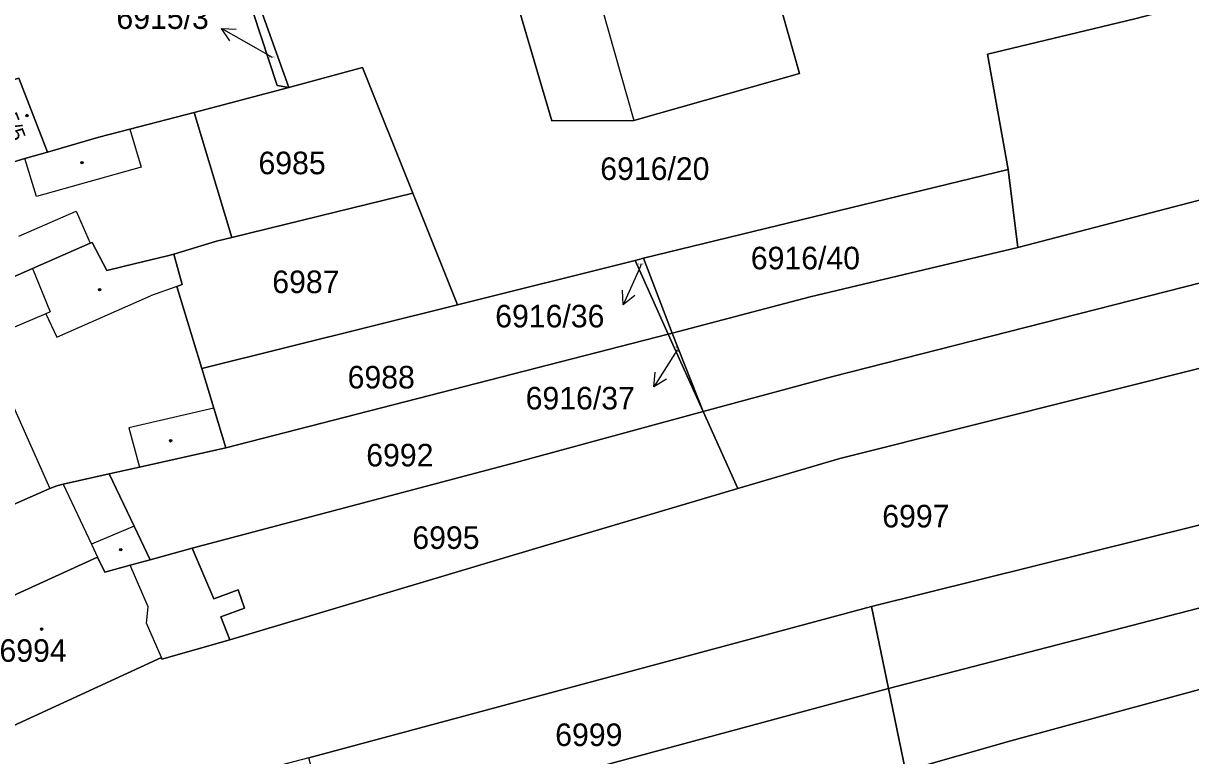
# Model space of a CAD drawing. Extents: x -596233 to -595156, y -1161235 to -1159375.
# Drawn here: x -595331.7 to -595243.9, y -1160372.2 to -1160317 of the extents above; entities that cross this region are included whole.
import ezdxf

# ---------------------------------------------------------------- set-up
doc = ezdxf.new("R2010")
doc.units = 0
for name, color, linetype in [('KN_CAR_KR', 7, 'Continuous'), ('KN_KULTURY', 7, 'Continuous'), ('KN_PARC_CIS_POM', 7, 'Continuous'), ('KN_PARC_CIS_POZ', 7, 'Continuous'), ('KN_PARC_CIS_STAV', 7, 'Continuous'), ('KN_PARC_PLOCHA', 7, 'Continuous'), ('PARC_C_SIPKA', 7, 'Continuous'), ('parcely_l', 7, 'Continuous')]:
    doc.layers.add(name, color=color, linetype=linetype)

msp = doc.modelspace()

# ---------------------------------------------------------------- linework, layer by layer
at = {"layer": 'KN_CAR_KR'}
for points in [[(-595290.5, -1160307.71), (-595285.79, -1160324.36)], [(-595323.72, -1160325.02), (-595322.86, -1160327.88)], [(-595330.75, -1160330.09), (-595331.62, -1160327.22)], [(-595322.86, -1160327.88), (-595330.75, -1160330.09)], [(-595332.06, -1160333.07), (-595327.76, -1160331.18)], [(-595327.76, -1160331.18), (-595326.69, -1160333.61)], [(-595331.05, -1160335.51), (-595329.7, -1160338.77)], [(-595320.18, -1160336.85), (-595322.15, -1160337.57)], [(-595329.21, -1160340.67), (-595322.15, -1160337.57)], [(-595330.03, -1160338.91), (-595334.73, -1160340.9)], [(-595329.7, -1160338.77), (-595330.03, -1160338.91)], [(-595330.03, -1160338.91), (-595329.21, -1160340.67)], [(-595334.73, -1160340.9), (-595329.73, -1160352.08)], [(-595317.4, -1160346.03), (-595323.78, -1160347.51)], [(-595323.78, -1160347.51), (-595323, -1160350.46)], [(-595328.73, -1160351.75), (-595326.59, -1160356.27)], [(-595323.38, -1160354.91), (-595326.59, -1160356.27)], [(-595326.59, -1160356.27), (-595326.14, -1160357.23)], [(-595322.33, -1160360.97), (-595323.68, -1160357.84)], [(-595322.47, -1160362.21), (-595322.33, -1160360.97)], [(-595321.34, -1160364.8), (-595322.47, -1160362.21)]]:
    msp.add_lwpolyline(points, dxfattribs=at)
at = {"layer": 'KN_KULTURY'}
for centre, radius in [((-595331.46, -1160323.99), 0.09), ((-595331.46, -1160323.99), 0.0398), ((-595327.31, -1160327.54), 0.09), ((-595327.31, -1160327.54), 0.0398), ((-595325.99, -1160337.1), 0.09), ((-595325.99, -1160337.1), 0.0398), ((-595320.65, -1160348.48), 0.09), ((-595320.65, -1160348.48), 0.0398), ((-595324.4, -1160356.68), 0.09), ((-595324.4, -1160356.68), 0.0398), ((-595330.36, -1160362.66), 0.09), ((-595330.36, -1160362.66), 0.0398)]:
    msp.add_circle(centre, radius, dxfattribs=at)
at = {"layer": 'KN_PARC_PLOCHA'}
for points in [[(-595326.08, -1160281.97), (-595323.99, -1160287.92), (-595322, -1160293.27), (-595321.7, -1160294.07), (-595312.63, -1160321.74), (-595311.75, -1160321.89), (-595318.88, -1160323.75), (-595323.72, -1160325.02), (-595326.04, -1160325.63), (-595329.91, -1160326.74), (-595332.08, -1160321.19), (-595334.71, -1160321.94), (-595337.01, -1160322.6), (-595346.85, -1160300.58), (-595351.35, -1160290.65), (-595352.68, -1160287.85), (-595328.36, -1160276.46)], [(-595275.52, -1160298.61), (-595273.4, -1160306.13), (-595277.16, -1160307.25), (-595273.32, -1160320.83), (-595285.79, -1160324.36), (-595291.95, -1160324.4), (-595296.39, -1160309.27), (-595296.06, -1160309.19), (-595297.11, -1160305.25), (-595291.63, -1160303.69), (-595295.08, -1160291.51), (-595295.59, -1160289.7), (-595283.15, -1160286.13), (-595279.31, -1160299.71)], [(-595311.75, -1160321.89), (-595312.63, -1160321.74), (-595321.7, -1160294.07)], [(-595199.64, -1160320.07), (-595225.81, -1160325.82), (-595256.9, -1160333.93), (-595257.62, -1160328.05), (-595259.17, -1160319.36), (-595248.1, -1160316.7), (-595204.23, -1160305.26), (-595199.79, -1160319.6)], [(-595197.73, -1160326.01), (-595198.12, -1160326.1), (-595224.64, -1160331.86), (-595270.82, -1160343.63), (-595280.58, -1160346.28), (-595282.9, -1160340.37), (-595272.51, -1160337.64), (-595256.9, -1160333.93), (-595225.81, -1160325.82), (-595199.64, -1160320.07)], [(-595302.43, -1160329.84), (-595308.16, -1160331.23), (-595316.04, -1160333.18), (-595318.88, -1160323.75), (-595311.75, -1160321.89), (-595306.22, -1160320.38)], [(-595329.91, -1160326.74), (-595331.62, -1160327.22), (-595332.53, -1160327.51), (-595334.71, -1160321.94), (-595332.08, -1160321.19)], [(-595316.04, -1160333.18), (-595317.19, -1160333.46), (-595320.41, -1160334.42), (-595320.87, -1160334.56), (-595323.28, -1160335.14), (-595325.46, -1160335.65), (-595326.55, -1160333.55), (-595326.69, -1160333.61), (-595331.05, -1160335.51), (-595346.11, -1160342.16), (-595349.74, -1160343.8), (-595353.8, -1160334.66), (-595350.18, -1160333.07), (-595340.58, -1160328.81), (-595339.18, -1160328.19), (-595338.7, -1160329.24), (-595337.35, -1160328.93), (-595334.83, -1160328.19), (-595332.53, -1160327.51), (-595331.62, -1160327.22), (-595329.91, -1160326.74), (-595326.04, -1160325.63), (-595323.72, -1160325.02), (-595318.88, -1160323.75)], [(-595185.74, -1160328.7), (-595221.55, -1160337.59), (-595222.15, -1160337.73), (-595270.28, -1160349.8), (-595277.97, -1160352.08), (-595280.58, -1160346.28), (-595270.82, -1160343.63), (-595224.64, -1160331.86), (-595198.12, -1160326.1), (-595197.73, -1160326.01), (-595186.79, -1160323.7)], [(-595256.9, -1160333.93), (-595272.51, -1160337.64), (-595282.9, -1160340.37), (-595285.06, -1160334.74), (-595257.62, -1160328.05)], [(-595183.45, -1160340.15), (-595190.6, -1160342), (-595218.83, -1160349.08), (-595235.21, -1160352.82), (-595267.91, -1160360.96), (-595287.01, -1160366.11), (-595310.25, -1160372.35), (-595319.06, -1160374.66), (-595319.29, -1160374.12), (-595329.8, -1160378.6), (-595333.45, -1160380.19), (-595334.01, -1160378.85), (-595337.16, -1160372.02), (-595333.5, -1160370.39), (-595321.34, -1160364.8), (-595321.3, -1160364.93), (-595316.2, -1160363.46), (-595293.44, -1160356.66), (-595277.97, -1160352.08), (-595270.28, -1160349.8), (-595222.15, -1160337.73), (-595221.55, -1160337.59), (-595185.74, -1160328.7), (-595184.81, -1160333.13)], [(-595299.06, -1160338.24), (-595318.31, -1160343.04), (-595320.18, -1160336.85), (-595319.78, -1160336.7), (-595320.41, -1160334.42), (-595317.19, -1160333.46), (-595316.04, -1160333.18), (-595308.16, -1160331.23), (-595302.43, -1160329.84)], [(-595320.41, -1160334.42), (-595319.78, -1160336.7), (-595320.18, -1160336.85), (-595318.31, -1160343.04), (-595317.4, -1160346.03), (-595316.5, -1160349), (-595323, -1160350.46), (-595325.26, -1160350.97), (-595328.73, -1160351.75), (-595329.22, -1160351.86), (-595329.73, -1160352.08), (-595339.72, -1160356.45), (-595343.39, -1160358.09), (-595343.75, -1160357.27), (-595346.82, -1160350.38), (-595349.74, -1160343.8), (-595346.11, -1160342.16), (-595331.05, -1160335.51), (-595326.69, -1160333.61), (-595326.55, -1160333.55), (-595325.46, -1160335.65), (-595323.28, -1160335.14), (-595320.87, -1160334.56)], [(-595283.2, -1160340.44), (-595316.5, -1160349), (-595317.4, -1160346.03), (-595318.31, -1160343.04), (-595299.06, -1160338.24), (-595285.69, -1160334.9)], [(-595282.9, -1160340.37), (-595283.2, -1160340.44), (-595285.69, -1160334.9), (-595285.06, -1160334.74)], [(-595181.98, -1160345.08), (-595182.2, -1160345.14), (-595217.32, -1160354.36), (-595266.63, -1160367.14), (-595267.91, -1160360.96), (-595235.21, -1160352.82), (-595218.83, -1160349.08), (-595190.6, -1160342), (-595183.45, -1160340.15)], [(-595280.58, -1160346.28), (-595294.67, -1160350.12), (-595319.03, -1160356.56), (-595322.18, -1160357.43), (-595323.38, -1160354.91), (-595325.26, -1160350.97), (-595323, -1160350.46), (-595316.5, -1160349), (-595283.2, -1160340.44)], [(-595280.58, -1160346.28), (-595283.2, -1160340.44), (-595282.9, -1160340.37)], [(-595180.48, -1160350.12), (-595180.96, -1160350.25), (-595215.76, -1160359.73), (-595257.42, -1160371.07), (-595265.35, -1160373.32), (-595266.63, -1160367.14), (-595217.32, -1160354.36), (-595182.2, -1160345.14), (-595181.98, -1160345.08)], [(-595277.97, -1160352.08), (-595293.44, -1160356.66), (-595316.2, -1160363.46), (-595316.87, -1160361.73), (-595315.08, -1160361.08), (-595315.57, -1160359.71), (-595317.39, -1160360.37), (-595319.03, -1160356.56), (-595294.67, -1160350.12), (-595280.58, -1160346.28)], [(-595178.52, -1160356.69), (-595189.16, -1160365.42), (-595206.78, -1160371.83), (-595211.45, -1160373.16), (-595228.41, -1160378.24), (-595248.43, -1160384.37), (-595259.37, -1160388), (-595265.35, -1160373.32), (-595257.42, -1160371.07), (-595215.76, -1160359.73), (-595180.96, -1160350.25), (-595180.48, -1160350.12)], [(-595322.18, -1160357.43), (-595323.68, -1160357.84), (-595325.6, -1160358.37), (-595326.14, -1160357.23), (-595337.17, -1160362.26), (-595340.77, -1160363.87), (-595341.12, -1160363.1), (-595343.39, -1160358.09), (-595339.72, -1160356.45), (-595329.73, -1160352.08), (-595329.22, -1160351.86), (-595328.73, -1160351.75), (-595325.26, -1160350.97), (-595323.38, -1160354.91)], [(-595316.2, -1160363.46), (-595321.3, -1160364.93), (-595321.34, -1160364.8), (-595333.5, -1160370.39), (-595337.16, -1160372.02), (-595338.5, -1160369), (-595340.77, -1160363.87), (-595337.17, -1160362.26), (-595326.14, -1160357.23), (-595325.6, -1160358.37), (-595323.68, -1160357.84), (-595322.18, -1160357.43), (-595319.03, -1160356.56), (-595317.39, -1160360.37), (-595315.57, -1160359.71), (-595315.08, -1160361.08), (-595316.87, -1160361.73)], [(-595266.63, -1160367.14), (-595305.36, -1160377.59), (-595308.83, -1160378.49), (-595309.58, -1160374.91), (-595310.25, -1160372.35), (-595287.01, -1160366.11), (-595267.91, -1160360.96)], [(-595265.35, -1160373.32), (-595283, -1160378.34), (-595294.19, -1160381.29), (-595300.54, -1160382.93), (-595303.63, -1160383.72), (-595304.09, -1160381.87), (-595305.36, -1160377.59), (-595266.63, -1160367.14)]]:
    msp.add_lwpolyline(points, close=True, dxfattribs=at)
for points in [[(-595248.1, -1160316.7), (-595259.17, -1160319.36), (-595257.62, -1160328.05), (-595285.06, -1160334.74), (-595285.69, -1160334.9), (-595299.06, -1160338.24), (-595302.43, -1160329.84), (-595306.22, -1160320.38), (-595311.75, -1160321.89), (-595321.7, -1160294.07)], [(-595296.39, -1160309.27), (-595291.95, -1160324.4), (-595285.79, -1160324.36), (-595273.32, -1160320.83), (-595277.16, -1160307.25)]]:
    msp.add_lwpolyline(points, dxfattribs=at)
at = {"layer": 'PARC_C_SIPKA'}
for points in [[(-595316.2039, -1160318.3596), (-595316.8231, -1160317.4287), (-595315.7068, -1160317.4919)], [(-595312.98, -1160319.63), (-595314.22, -1160318.92), (-595316.8231, -1160317.4287)], [(-595285.24, -1160335.21), (-595285.37, -1160335.5), (-595286.5834, -1160338.2437)], [(-595285.7216, -1160337.5313), (-595286.5834, -1160338.2437), (-595286.6362, -1160337.1269)], [(-595282.54, -1160341.68), (-595282.68, -1160341.89), (-595284.2948, -1160344.4183)], [(-595283.3351, -1160343.8447), (-595284.2948, -1160344.4183), (-595284.1779, -1160343.3064)]]:
    msp.add_lwpolyline(points, dxfattribs=at)
at = {"layer": 'parcely_l'}
for points in [[(-595295.08, -1160291.51), (-595291.63, -1160303.69), (-595297.11, -1160305.25), (-595296.06, -1160309.19), (-595296.39, -1160309.27), (-595291.95, -1160324.4), (-595285.79, -1160324.36), (-595273.32, -1160320.83), (-595277.16, -1160307.25), (-595273.4, -1160306.13)], [(-595311.75, -1160321.89), (-595321.7, -1160294.07)], [(-595321.7, -1160294.07), (-595312.63, -1160321.74), (-595311.75, -1160321.89)], [(-595204.23, -1160305.26), (-595248.1, -1160316.7), (-595259.17, -1160319.36), (-595257.62, -1160328.05)], [(-595256.9, -1160333.93), (-595225.81, -1160325.82), (-595199.64, -1160320.07)], [(-595302.43, -1160329.84), (-595306.22, -1160320.38), (-595311.75, -1160321.89)], [(-595334.71, -1160321.94), (-595332.08, -1160321.19), (-595329.91, -1160326.74)], [(-595318.88, -1160323.75), (-595311.75, -1160321.89)], [(-595329.91, -1160326.74), (-595326.04, -1160325.63), (-595323.72, -1160325.02), (-595318.88, -1160323.75)], [(-595318.88, -1160323.75), (-595316.04, -1160333.18)], [(-595280.58, -1160346.28), (-595270.82, -1160343.63), (-595224.64, -1160331.86), (-595198.12, -1160326.1), (-595197.73, -1160326.01)], [(-595332.53, -1160327.51), (-595331.62, -1160327.22), (-595329.91, -1160326.74)], [(-595257.62, -1160328.05), (-595285.06, -1160334.74)], [(-595257.62, -1160328.05), (-595256.9, -1160333.93)], [(-595185.74, -1160328.7), (-595221.55, -1160337.59), (-595222.15, -1160337.73), (-595270.28, -1160349.8), (-595277.97, -1160352.08)], [(-595302.43, -1160329.84), (-595308.16, -1160331.23), (-595316.04, -1160333.18)], [(-595299.06, -1160338.24), (-595302.43, -1160329.84)], [(-595316.04, -1160333.18), (-595317.19, -1160333.46), (-595320.41, -1160334.42)], [(-595320.41, -1160334.42), (-595320.87, -1160334.56), (-595323.28, -1160335.14), (-595325.46, -1160335.65), (-595326.55, -1160333.55), (-595326.69, -1160333.61), (-595331.05, -1160335.51), (-595346.11, -1160342.16), (-595349.74, -1160343.8)], [(-595256.9, -1160333.93), (-595272.51, -1160337.64), (-595282.9, -1160340.37)], [(-595320.41, -1160334.42), (-595319.78, -1160336.7), (-595320.18, -1160336.85), (-595318.31, -1160343.04)], [(-595285.69, -1160334.9), (-595299.06, -1160338.24)], [(-595285.06, -1160334.74), (-595285.69, -1160334.9)], [(-595285.69, -1160334.9), (-595283.2, -1160340.44)], [(-595282.9, -1160340.37), (-595285.06, -1160334.74)], [(-595318.31, -1160343.04), (-595299.06, -1160338.24)], [(-595267.91, -1160360.96), (-595235.21, -1160352.82), (-595218.83, -1160349.08), (-595190.6, -1160342), (-595183.45, -1160340.15)], [(-595283.2, -1160340.44), (-595316.5, -1160349)], [(-595283.2, -1160340.44), (-595282.9, -1160340.37)], [(-595280.58, -1160346.28), (-595283.2, -1160340.44)], [(-595282.9, -1160340.37), (-595280.58, -1160346.28)], [(-595316.5, -1160349), (-595317.4, -1160346.03), (-595318.31, -1160343.04)], [(-595181.98, -1160345.08), (-595182.2, -1160345.14), (-595217.32, -1160354.36), (-595266.63, -1160367.14)], [(-595319.03, -1160356.56), (-595294.67, -1160350.12), (-595280.58, -1160346.28)], [(-595280.58, -1160346.28), (-595277.97, -1160352.08)], [(-595325.26, -1160350.97), (-595323, -1160350.46), (-595316.5, -1160349)], [(-595265.35, -1160373.32), (-595257.42, -1160371.07), (-595215.76, -1160359.73), (-595180.96, -1160350.25), (-595180.48, -1160350.12)], [(-595343.39, -1160358.09), (-595339.72, -1160356.45), (-595329.73, -1160352.08), (-595329.22, -1160351.86), (-595328.73, -1160351.75), (-595325.26, -1160350.97)], [(-595325.26, -1160350.97), (-595323.38, -1160354.91), (-595322.18, -1160357.43)], [(-595277.97, -1160352.08), (-595293.44, -1160356.66), (-595316.2, -1160363.46)], [(-595322.18, -1160357.43), (-595319.03, -1160356.56)], [(-595316.2, -1160363.46), (-595316.87, -1160361.73), (-595315.08, -1160361.08), (-595315.57, -1160359.71), (-595317.39, -1160360.37), (-595319.03, -1160356.56)], [(-595322.18, -1160357.43), (-595323.68, -1160357.84), (-595325.6, -1160358.37), (-595326.14, -1160357.23), (-595337.17, -1160362.26), (-595340.77, -1160363.87)], [(-595267.91, -1160360.96), (-595287.01, -1160366.11), (-595310.25, -1160372.35)], [(-595266.63, -1160367.14), (-595267.91, -1160360.96)], [(-595316.2, -1160363.46), (-595321.3, -1160364.93), (-595321.34, -1160364.8), (-595333.5, -1160370.39), (-595337.16, -1160372.02)], [(-595305.36, -1160377.59), (-595266.63, -1160367.14)], [(-595265.35, -1160373.32), (-595266.63, -1160367.14)]]:
    msp.add_lwpolyline(points, dxfattribs=at)

# ---------------------------------------------------------------- texts
at = {"layer": 'KN_PARC_CIS_POM'}
for s, p in [('6915/3', (-595313.2633, -1160319.63)), ('6916/36', (-595285.5733, -1160335.21))]:
    msp.add_text(s, height=0.1, dxfattribs=at).set_placement(p)
msp.add_text('6916/37', height=0.1, rotation=289.739725, dxfattribs=at).set_placement((-595282.6526, -1160341.3663))
at = {"layer": 'KN_PARC_CIS_POZ'}
for s, p in [('6915/3', (-595324.7266, -1160317.47)), ('6985', (-595314.0366, -1160328.41)), ('6916/20', (-595288.3166, -1160328.84)), ('6916/40', (-595276.9866, -1160335.57)), ('6987', (-595312.9966, -1160337.36)), ('6916/36', (-595296.2216, -1160339.94)), ('6988', (-595307.3266, -1160344.54)), ('6916/37', (-595293.9316, -1160346.12)), ('6992', (-595305.9266, -1160350.41)), ('6997', (-595267.0966, -1160355)), ('6995', (-595302.4566, -1160356.62)), ('6999', (-595291.7066, -1160371.46))]:
    msp.add_text(s, height=1.7, dxfattribs=at).set_placement(p)
at = {"layer": 'KN_PARC_CIS_STAV'}
msp.add_text('6915/5', height=1.14, rotation=290.851519, dxfattribs=at).set_placement((-595334.2397, -1160321.6516))
msp.add_text('6994', height=1.7, dxfattribs=at).set_placement((-595333.5266, -1160365.12))

doc.saveas('drawing.dxf')
